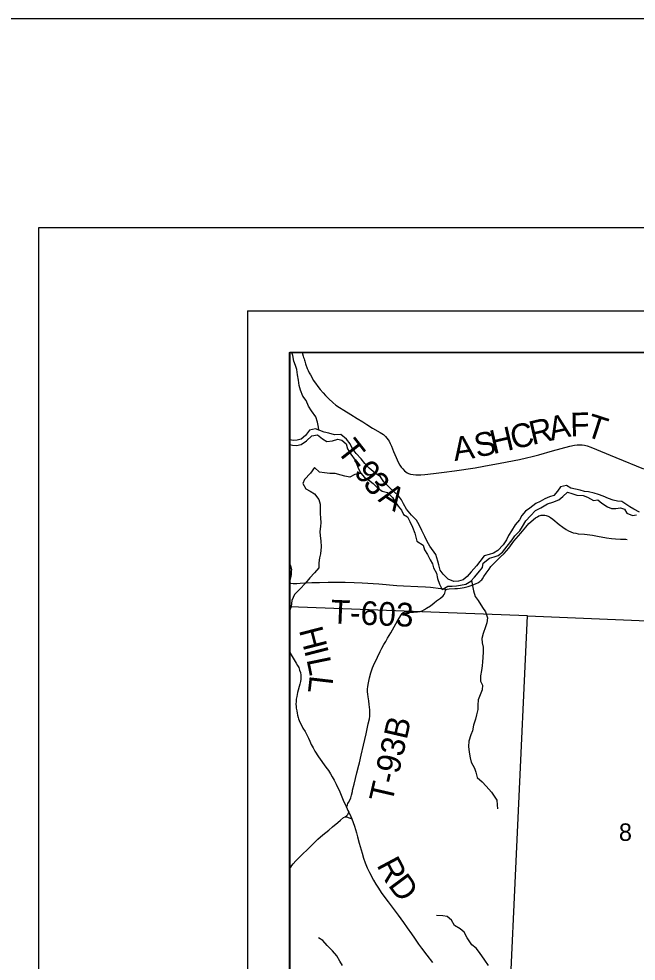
# Model space of a CAD drawing. Extents: x 0 to 34, y 0 to 22.
# Drawn here: x 1.952 to 3.431, y 19.741 to 22 of the extents above; entities that cross this region are included whole.
import ezdxf

# ---------------------------------------------------------------- set-up
doc = ezdxf.new("R2010")
doc.units = 0
for name, color, linetype in [('GM_X_County', 7, 'Continuous'), ('GM_X_County_Road', 7, 'Continuous'), ('GM_X_County_Road_Text', 7, 'Continuous'), ('GM_X_Minor_River', 7, 'Continuous'), ('GM_X_Section', 7, 'Continuous'), ('GM_X_Section_Text', 7, 'Continuous'), ('GM_X_Township', 7, 'Continuous'), ('GM_X_Township_Road', 7, 'Continuous'), ('GM_X_Township_Road_Text', 7, 'Continuous'), ('SH_Border', 7, 'Continuous'), ('SH_Cut_Line', 7, 'Continuous'), ('SH_Data', 7, 'Continuous')]:
    doc.layers.add(name, color=color, linetype=linetype)

msp = doc.modelspace()

# ---------------------------------------------------------------- linework, layer by layer
at = {"layer": 'GM_X_County'}
msp.add_lwpolyline([(7.0736, 21.2003), (2.6013, 21.2003), (2.6013, 14.4003), (9.4013, 14.4003), (9.4013, 21.1598)], dxfattribs=at)
at = {"layer": 'GM_X_County_Road'}
for points in [[(2.6013, 20.6922), (2.6018, 20.6909), (2.6036, 20.6859), (2.6046, 20.683), (2.6049, 20.6793), (2.6048, 20.676), (2.6044, 20.6725), (2.6041, 20.6688), (2.6033, 20.6627), (2.6013, 20.6544)], [(2.6013, 20.4806), (2.6067, 20.4709), (2.6165, 20.4552), (2.6199, 20.4497), (2.6226, 20.4446), (2.6248, 20.4388), (2.6265, 20.4327), (2.6276, 20.4266), (2.6278, 20.4235), (2.6276, 20.4172), (2.6267, 20.4111), (2.6252, 20.405), (2.6198, 20.385), (2.6178, 20.3754), (2.6168, 20.3689), (2.6162, 20.3631), (2.616, 20.3571), (2.6164, 20.3517), (2.6168, 20.3473), (2.6178, 20.3407), (2.6189, 20.3354), (2.6199, 20.3304), (2.6212, 20.3247), (2.6222, 20.322), (2.6256, 20.3135), (2.6282, 20.3079), (2.6324, 20.2996), (2.6377, 20.2912), (2.6428, 20.2815), (2.6456, 20.2757), (2.6488, 20.2681), (2.6526, 20.2602), (2.6568, 20.252), (2.6615, 20.2439), (2.67, 20.231), (2.6875, 20.2062), (2.6935, 20.1978), (2.6983, 20.1897), (2.7027, 20.1829), (2.7072, 20.1747), (2.712, 20.1654), (2.7209, 20.1471), (2.7293, 20.1271), (2.7355, 20.1129), (2.7368, 20.1101)], [(2.7368, 20.1101), (2.7406, 20.1017), (2.7425, 20.0978)], [(2.6013, 19.9631), (2.6033, 19.9665), (2.606, 19.97), (2.6091, 19.974), (2.6153, 19.981), (2.6218, 19.9877), (2.6529, 20.018), (2.6619, 20.027), (2.6686, 20.0333), (2.6805, 20.0437), (2.6943, 20.0552), (2.7037, 20.0627), (2.7161, 20.0735), (2.7226, 20.0792), (2.7301, 20.0849), (2.7341, 20.0872)], [(2.7341, 20.0872), (2.737, 20.0892), (2.7386, 20.0908), (2.7399, 20.0925), (2.7409, 20.0939), (2.7425, 20.0978)], [(2.7341, 20.0872), (2.7377, 20.0867), (2.741, 20.0856), (2.7435, 20.0846), (2.7455, 20.0835), (2.7501, 20.082)], [(2.7425, 20.0978), (2.7473, 20.0878), (2.7501, 20.082)], [(2.7501, 20.082), (2.7533, 20.0736), (2.756, 20.0647), (2.7607, 20.0486), (2.7634, 20.0387), (2.7676, 20.0237), (2.7744, 19.9995), (2.7778, 19.9879), (2.782, 19.9762), (2.7867, 19.9647), (2.7923, 19.9532), (2.8017, 19.9347), (2.807, 19.9257), (2.8117, 19.9184), (2.822, 19.9034), (2.8367, 19.8834), (2.8607, 19.851), (2.8734, 19.8333), (2.8824, 19.8206), (2.8925, 19.8065), (2.8996, 19.7963), (2.9098, 19.7816), (2.9169, 19.7723), (2.9295, 19.7551), (2.9428, 19.7379)]]:
    msp.add_lwpolyline(points, dxfattribs=at)
at = {"layer": 'GM_X_Minor_River'}
for points in [[(2.6711, 21.0138), (2.6699, 21.0207), (2.6675, 21.0329), (2.6637, 21.0462), (2.6534, 21.0602), (2.6461, 21.0712), (2.64, 21.0852), (2.6324, 21.095), (2.627, 21.1094), (2.6239, 21.1208), (2.622, 21.1341), (2.6196, 21.1466), (2.6177, 21.1591), (2.6146, 21.169), (2.6112, 21.1789), (2.6084, 21.1925), (2.606, 21.2003)], [(3.2859, 20.8721), (3.2741, 20.8751), (3.2639, 20.8811), (3.2498, 20.8781), (3.2427, 20.8674), (3.2336, 20.8575), (3.2234, 20.8537), (3.212, 20.8491), (3.2007, 20.8426), (3.1904, 20.838), (3.1761, 20.8269), (3.1659, 20.8197), (3.1572, 20.809), (3.1515, 20.7988), (3.141, 20.7866), (3.1323, 20.7725), (3.1251, 20.7615), (3.1206, 20.7512), (3.1127, 20.739), (3.0995, 20.7257), (3.0889, 20.7192), (3.079, 20.7154), (3.0669, 20.7123), (3.0563, 20.699), (3.0488, 20.6883), (3.0356, 20.6746), (3.0265, 20.6632), (3.0167, 20.6552), (3.0057, 20.6521), (2.9939, 20.6513), (2.9802, 20.657), (2.9688, 20.6687), (2.9612, 20.6785), (2.9585, 20.6907), (2.9558, 20.7002), (2.9512, 20.7157), (2.9363, 20.7358), (2.9302, 20.7471), (2.9248, 20.7589), (2.9175, 20.7737), (2.911, 20.7873), (2.9049, 20.7979), (2.8931, 20.8097), (2.8805, 20.8248), (2.8736, 20.8369), (2.8687, 20.8468), (2.8618, 20.8566), (2.8511, 20.8657), (2.8397, 20.8763), (2.8267, 20.8903), (2.8183, 20.902), (2.8058, 20.9111), (2.7913, 20.9225), (2.7806, 20.9338), (2.7719, 20.9448), (2.7604, 20.958), (2.7509, 20.9705), (2.7459, 20.9808), (2.7368, 20.9921), (2.7238, 21.0031), (2.7083, 21.0023), (2.6946, 21.0068), (2.6832, 21.009), (2.6631, 21.0169), (2.6487, 21.0135), (2.6388, 21.0009), (2.6283, 20.9925), (2.6188, 20.9902), (2.6093, 20.9887), (2.6013, 20.991)], [(2.6013, 20.9793), (2.6074, 20.9776), (2.6169, 20.9773), (2.6283, 20.9796), (2.6412, 20.9884), (2.654, 21.0002), (2.6677, 21.0025), (2.6799, 20.9934), (2.6901, 20.9866), (2.7034, 20.9882), (2.7163, 20.9921), (2.7262, 20.9898), (2.7361, 20.9815), (2.7395, 20.9694), (2.7472, 20.9565), (2.7575, 20.9421), (2.7617, 20.9318), (2.7659, 20.9209), (2.7716, 20.911), (2.7804, 20.9), (2.7899, 20.8944), (2.8006, 20.8864), (2.8112, 20.8758), (2.8227, 20.8679), (2.8352, 20.8641), (2.8474, 20.8528), (2.8535, 20.8422), (2.8611, 20.8316), (2.8684, 20.8217), (2.8737, 20.8119), (2.8832, 20.8058), (2.8886, 20.7952), (2.8951, 20.7812), (2.9005, 20.7672), (2.9028, 20.7573), (2.9059, 20.7478), (2.9203, 20.7384), (2.9238, 20.7266), (2.931, 20.7156), (2.9372, 20.7028), (2.9429, 20.6933), (2.9452, 20.6838), (2.9529, 20.6713), (2.9552, 20.658), (2.9602, 20.6444), (2.9659, 20.6319), (2.9799, 20.6399), (2.9902, 20.6395), (3.0008, 20.6407), (3.0103, 20.6423), (3.0228, 20.645), (3.0349, 20.6518), (3.044, 20.6617), (3.0523, 20.6716), (3.0625, 20.6846), (3.0647, 20.6952), (3.0798, 20.7067), (3.0904, 20.7105), (3.1007, 20.7136), (3.1109, 20.7216)], [(2.7727, 20.9097), (2.7569, 20.9072), (2.7451, 20.9014), (2.7333, 20.9037), (2.7239, 20.9059), (2.7098, 20.9097), (2.6973, 20.9096), (2.6847, 20.9118), (2.6726, 20.9133), (2.66, 20.9243), (2.6506, 20.9106), (2.6366, 20.8957), (2.6321, 20.8862), (2.6398, 20.873), (2.6496, 20.8677), (2.6603, 20.8613), (2.671, 20.848), (2.6741, 20.8366), (2.6741, 20.8142), (2.6746, 20.8032), (2.6754, 20.7926), (2.6747, 20.7831), (2.6732, 20.771), (2.674, 20.7603), (2.6752, 20.7486), (2.676, 20.7345), (2.6746, 20.7171), (2.6727, 20.7076), (2.6708, 20.6958), (2.6705, 20.684), (2.6603, 20.6718), (2.6494, 20.66), (2.6388, 20.6471), (2.6252, 20.633), (2.6123, 20.62), (2.606, 20.6056), (2.6041, 20.5915), (2.6013, 20.5821)], [(3.1109, 20.7216), (3.1222, 20.736), (3.1343, 20.7509), (3.1407, 20.7608), (3.152, 20.7722), (3.1584, 20.7832), (3.1667, 20.7962), (3.1777, 20.8087), (3.1898, 20.8213), (3.2026, 20.8278), (3.2189, 20.8373), (3.231, 20.8415), (3.2454, 20.8465), (3.2556, 20.8549), (3.2666, 20.8652), (3.2765, 20.8618), (3.289, 20.8581), (3.3042, 20.857), (3.3148, 20.8532), (3.3289, 20.8453), (3.3391, 20.8468), (3.349, 20.8389), (3.362, 20.8298), (3.3719, 20.8261), (3.3825, 20.8261), (3.3935, 20.828), (3.403, 20.8247), (3.4087, 20.8152), (3.422, 20.8092), (3.4319, 20.8111)], [(3.4387, 20.8172), (3.4257, 20.8244), (3.4155, 20.83), (3.406, 20.8364), (3.3965, 20.8425), (3.3866, 20.8436), (3.3763, 20.8458), (3.3646, 20.85), (3.3516, 20.856), (3.3406, 20.8594), (3.33, 20.8631), (3.3167, 20.8658), (3.3072, 20.8672), (3.2969, 20.8699), (3.2859, 20.8721)], [(3.0366, 20.6537), (3.0411, 20.6283), (3.0449, 20.6154), (3.0525, 20.6052), (3.0632, 20.5889), (3.0701, 20.5783), (3.0747, 20.5639), (3.0733, 20.5517), (3.0703, 20.5422), (3.0646, 20.5263), (3.0616, 20.5145), (3.0624, 20.5039), (3.0648, 20.494), (3.0648, 20.4822), (3.0637, 20.4689), (3.063, 20.4587), (3.0619, 20.4492), (3.0608, 20.4374), (3.0582, 20.4245), (3.0583, 20.412), (3.0629, 20.4025), (3.0618, 20.3915), (3.0573, 20.3793), (3.0524, 20.3675), (3.0513, 20.3546), (3.0517, 20.3444), (3.0484, 20.3315), (3.0458, 20.3212), (3.0416, 20.3068), (3.039, 20.2927), (3.0349, 20.2832), (3.0304, 20.268), (3.029, 20.2551), (3.0313, 20.2422), (3.0329, 20.2281), (3.0359, 20.2183), (3.0436, 20.2039), (3.0467, 20.194), (3.0501, 20.1815), (3.0623, 20.1709), (3.0718, 20.1607), (3.0848, 20.1463), (3.0905, 20.1365), (3.097, 20.1266), (3.0982, 20.116), (3.099, 20.1057)], [(3.077, 19.7306), (3.0683, 19.7435), (3.056, 19.7613), (3.0477, 19.7719), (3.0374, 19.7802), (3.0263, 19.7968), (3.0187, 19.8101), (3.0091, 19.818), (2.9958, 19.8267), (2.9882, 19.8389), (2.9783, 19.8476), (2.9677, 19.8494), (2.9525, 19.8505)], [(2.7272, 19.7305), (2.7211, 19.7412), (2.7142, 19.7533), (2.7035, 19.7654), (2.691, 19.7786), (2.6803, 19.7904), (2.6696, 19.7964)]]:
    msp.add_lwpolyline(points, dxfattribs=at)
at = {"layer": 'GM_X_Section'}
msp.add_line((2.6013, 20.5903), (2.6013, 19.5793), dxfattribs=at)
msp.add_lwpolyline([(2.6013, 19.5793), (3.1241, 19.5651), (3.1703, 20.5686), (2.6013, 20.5903)], dxfattribs=at)
msp.add_lwpolyline([(3.1703, 20.5686), (3.6876, 20.5473), (3.6799, 20.3833), (3.6562, 19.8796), (3.6414, 19.554), (3.1241, 19.5651)], close=True, dxfattribs=at)
at = {"layer": 'GM_X_Township'}
msp.add_lwpolyline([(6.2234, 21.2003), (2.6013, 21.2003), (2.6013, 16.5379)], dxfattribs=at)
at = {"layer": 'GM_X_Township_Road'}
for points in [[(2.6307, 21.2003), (2.6317, 21.1971), (2.6335, 21.1909), (2.6343, 21.1881), (2.6353, 21.1849), (2.6362, 21.1819), (2.637, 21.179), (2.6388, 21.1732), (2.6427, 21.1621), (2.6449, 21.1568), (2.6476, 21.1513), (2.6504, 21.1463), (2.6544, 21.1392), (2.6573, 21.1341), (2.6625, 21.1262), (2.668, 21.1184), (2.6741, 21.1111), (2.6809, 21.1032), (2.6867, 21.0969), (2.6948, 21.0889), (2.7042, 21.0802), (2.7117, 21.0742), (2.7204, 21.0681), (2.7308, 21.0615), (2.7474, 21.0516), (2.7628, 21.042), (2.776, 21.0336), (2.786, 21.0271), (2.7997, 21.0189), (2.8174, 21.0086), (2.8255, 21.0032), (2.8302, 20.9988), (2.8339, 20.995), (2.8367, 20.9909), (2.8391, 20.9871), (2.8418, 20.9821), (2.8448, 20.9757), (2.8495, 20.9628), (2.8558, 20.9483), (2.8609, 20.9371), (2.865, 20.9297), (2.8681, 20.925), (2.8716, 20.9211), (2.8756, 20.9165), (2.8793, 20.9138), (2.8822, 20.9119), (2.8857, 20.9101), (2.8903, 20.9084), (2.8964, 20.9075), (2.9028, 20.907), (2.9085, 20.9068), (2.9155, 20.9071), (2.9247, 20.9077), (2.9451, 20.9103), (2.971, 20.9134), (2.996, 20.9163), (3.0456, 20.9237), (3.0657, 20.9273), (3.1053, 20.935), (3.1516, 20.9439), (3.1679, 20.9474), (3.1817, 20.9505), (3.1981, 20.9549), (3.2304, 20.9643), (3.2512, 20.9703), (3.2719, 20.9755), (3.2833, 20.9778), (3.2893, 20.9787), (3.2954, 20.979), (3.3015, 20.9787), (3.3075, 20.9777), (3.3135, 20.9762), (3.3222, 20.9731), (3.3826, 20.9485), (3.4485, 20.9211)], [(2.9758, 20.6315), (2.9761, 20.632), (2.9779, 20.633), (2.9826, 20.6334), (2.9962, 20.634), (3.003, 20.6346), (3.0091, 20.6352), (3.0186, 20.6366), (3.0284, 20.6393), (3.0378, 20.642), (3.0473, 20.646), (3.0515, 20.6477), (3.054, 20.6492), (3.0564, 20.6511), (3.0588, 20.6531), (3.0609, 20.6554), (3.0629, 20.6577), (3.0664, 20.6628), (3.0718, 20.6712), (3.0787, 20.6809), (3.0831, 20.6869), (3.0901, 20.6946), (3.0965, 20.701), (3.1051, 20.7092), (3.1145, 20.7178), (3.126, 20.7311), (3.1379, 20.7477), (3.1549, 20.767), (3.1663, 20.7816), (3.1739, 20.7902), (3.1789, 20.7943), (3.1853, 20.7999), (3.19, 20.8034), (3.1945, 20.8062), (3.1978, 20.8081), (3.2007, 20.8093), (3.2036, 20.8099), (3.2064, 20.8103), (3.2098, 20.8103), (3.2119, 20.8099), (3.215, 20.8094), (3.2175, 20.8086), (3.22, 20.8077), (3.223, 20.8059), (3.2257, 20.8042), (3.2312, 20.8005), (3.2463, 20.7879), (3.2551, 20.7811), (3.2634, 20.7757), (3.2688, 20.7726), (3.2744, 20.77), (3.2803, 20.768), (3.2864, 20.7666), (3.2924, 20.7657), (3.3076, 20.7642), (3.3261, 20.762), (3.3384, 20.7598), (3.3598, 20.7559), (3.3721, 20.7542), (3.3814, 20.7533), (3.3938, 20.7528), (3.4031, 20.7525), (3.4062, 20.7522), (3.4091, 20.7517)], [(2.6013, 20.6476), (2.6028, 20.6473), (2.6092, 20.6463), (2.6134, 20.6461), (2.6177, 20.6464), (2.6264, 20.6473), (2.6371, 20.6482), (2.6538, 20.6485), (2.6723, 20.6487), (2.6929, 20.6495), (2.7159, 20.6493), (2.7338, 20.6492), (2.7557, 20.6485), (2.7742, 20.6477), (2.8148, 20.6453), (2.8578, 20.6418), (2.8734, 20.6407), (2.9076, 20.6394), (2.9262, 20.6384), (2.9386, 20.6372), (2.9633, 20.6339), (2.9694, 20.6334), (2.9728, 20.633), (2.9743, 20.6323), (2.9758, 20.6315)], [(2.7368, 20.1101), (2.7394, 20.1159), (2.7406, 20.1187), (2.7419, 20.1214), (2.7448, 20.1269), (2.7473, 20.1325), (2.749, 20.1384), (2.751, 20.1474), (2.7516, 20.1504), (2.7552, 20.1654), (2.7618, 20.1925), (2.7664, 20.2105), (2.7679, 20.2165), (2.7723, 20.2345), (2.778, 20.2586), (2.7838, 20.2857), (2.7893, 20.3099), (2.792, 20.3221), (2.7929, 20.3282), (2.7931, 20.3344), (2.7927, 20.3437), (2.7915, 20.3561), (2.7903, 20.3653), (2.7887, 20.3745), (2.788, 20.3806), (2.7876, 20.3868), (2.7877, 20.3929), (2.7883, 20.399), (2.7898, 20.4081), (2.7925, 20.4202), (2.7957, 20.4321), (2.7995, 20.4439), (2.8017, 20.4497), (2.8109, 20.4694), (2.8177, 20.4833), (2.8219, 20.4916), (2.8264, 20.4997), (2.8309, 20.5076), (2.8355, 20.5152), (2.8432, 20.5278), (2.8593, 20.5564), (2.8684, 20.5723), (2.8706, 20.5747), (2.8729, 20.5766), (2.8754, 20.5777), (2.8783, 20.5781), (2.8862, 20.5777), (2.8979, 20.5776), (2.9071, 20.5782), (2.9138, 20.579), (2.9181, 20.5806), (2.9239, 20.5837), (2.929, 20.5871), (2.9379, 20.593), (2.9467, 20.5999), (2.9524, 20.6044), (2.9574, 20.6079), (2.9619, 20.6108), (2.9687, 20.6163), (2.9713, 20.6198), (2.9724, 20.6227), (2.9733, 20.6264), (2.9743, 20.6296), (2.9758, 20.6315)]]:
    msp.add_lwpolyline(points, dxfattribs=at)
at = {"layer": 'SH_Border'}
msp.add_lwpolyline([(2, 21.5), (33.5, 21.5), (33.5, 0.5), (2, 0.5)], close=True, dxfattribs=at)
at = {"layer": 'SH_Cut_Line'}
msp.add_lwpolyline([(0, 0), (34, 0), (34, 22), (0, 22)], close=True, dxfattribs=at)
at = {"layer": 'SH_Data'}
for p, q in [((2.5, 21.2997), (9.5, 21.2997)), ((2.5, 21.2997), (2.5, 14.2997)), ((2.6, 21.1997), (2.6, 14.3997)), ((2.6, 21.1997), (9.4, 21.1997))]:
    msp.add_line(p, q, dxfattribs=at)

# ---------------------------------------------------------------- texts
at = {"layer": 'GM_X_County_Road_Text'}
for s, rotation, p in [('H', 284.5027, (2.6228, 20.5346)), ('I', 284.4528, (2.6353, 20.4862)), ('L', 281.6604, (2.641, 20.4643)), ('L', 263.39, (2.6493, 20.4275)), ('R', 298.1065, (2.8082, 19.9714)), ('D', 306.7081, (2.8351, 19.9226))]:
    msp.add_text(s, height=0.0568, rotation=rotation, dxfattribs=at).set_placement(p)
at = {"layer": 'GM_X_Section_Text'}
msp.add_text('8', height=0.0419, rotation=0, dxfattribs=at).set_placement((3.3897, 20.0292))
at = {"layer": 'GM_X_Township_Road_Text'}
for s, height, rotation, p in [('F', 0.0568, 1.3258, (3.2735, 20.9988)), ('R', 0.0568, 13.1067, (3.1822, 20.978)), ('A', 0.0568, 12.193, (3.2274, 20.9885)), ('T', 0.0568, 342.0285, (3.3068, 21.0004)), ('S', 0.0568, 12.0771, (3.0495, 20.9478)), ('H', 0.0568, 13.1022, (3.0881, 20.9561)), ('C', 0.0568, 13.124, (3.1368, 20.9674)), ('T', 0.0568, 308.1746, (2.7117, 20.9649)), ('A', 0.0568, 8.4382, (2.9961, 20.9398)), ('-', 0.0568, 308.2051, (2.738, 20.9314)), ('9', 0.0568, 308.3149, (2.7525, 20.913)), ('3', 0.0568, 308.8161, (2.7745, 20.8851)), ('A', 0.0568, 326.6766, (2.8107, 20.8449)), ('T-603', 0.05682, 357.6041, (2.6981, 20.5506)), ('T-93B', 0.05682, 77.0547, (2.8461, 20.1179))]:
    msp.add_text(s, height=height, rotation=rotation, dxfattribs=at).set_placement(p)

doc.saveas('drawing.dxf')
